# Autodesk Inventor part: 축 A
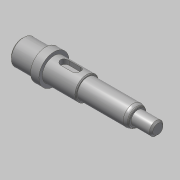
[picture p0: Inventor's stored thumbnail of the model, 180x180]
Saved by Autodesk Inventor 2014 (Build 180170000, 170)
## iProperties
Created: 2020-04
Part Number: 축 A
Material: 강철, 연강
Document SubType Name: Modeling
Designer: mduedu
Density: 7.86 g/cm^3
Appearance: 강철
Mass: 83.1664 g
Surface Area: 37.6212 cm^2
Volume: 10.581 cm^3
Author: mduedu
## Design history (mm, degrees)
sketch "스케치1"
  geometry: L1 (0, 0)-(14, 0); L2 (14, 0)-(14, 7.5); L3 (14, 7.5)-(0, 7.5); L4 (0, 7.5)-(0, 0); L5 (14, 0)-(19, 0); L6 (19, 0)-(19, 9); L7 (19, 9)-(14, 9); L8 (14, 9)-(14, 0); L9 (19, 0)-(39, 0); L10 (39, 0)-(39, 7); L11 (39, 7)-(19, 7); L12 (19, 7)-(19, 0); L13 (39, 0)-(69, 0); L14 (69, 0)-(69, 6); L15 (69, 6)-(39, 6); L16 (39, 6)-(39, 0); L17 (69, 0)-(81, 0); L18 (81, 0)-(81, 4); L19 (81, 4)-(69, 4); L20 (69, 4)-(69, 0)
  constraints: 40 end point, 10 parallel, 5 horizontal, 5 perpendicular
  dimensions: "d0" = 81 distance between parallel lines of L18 L4; "d2" = 14 distance of L2.end L3.end; "d3" = 5 distance of L6.end L7.end; "d4" = 12 distance of L18.end L19.end; "d5" = 8 diameter of L19 L17; "d6" = 12 diameter of L15 L13; "d7" = 14 diameter of L11 L9; "d8" = 15 diameter of L3 L1; "d9" = 18 diameter of L7 L5; "d10" = 42 distance between parallel lines of L10 L18
revolve "회전1" sketch "스케치1" stored, may be unused: angle "d11" = 90 deg
sketch "스케치2"
  geometry: L1 (0, -7.5)-(0, 7.5) reference; L2 (0, 7.5)-(14, 7.5) reference; L3 (14, 7.5)-(14, 9) reference; L4 (14, 9)-(19, 9) reference; L5 (19, 9)-(19, 7) reference; L6 (19, 7)-(39, 7) reference; L7 (39, 7)-(39, 6) reference; L8 (39, 6)-(69, 6) reference; L9 (69, 6)-(69, 4) reference; L10 (69, 4)-(81, 4) reference; L11 (81, 4)-(81, -4) reference; L12 (81, -4)-(69, -4) reference; L13 (69, -4)-(69, -6) reference; L14 (69, -6)-(39, -6) reference; L15 (39, -6)-(39, -7) reference; L16 (39, -7)-(19, -7) reference; L17 (19, -7)-(19, -9) reference; L18 (19, -9)-(14, -9) reference; L19 (14, -9)-(14, -7.5) reference; L20 (14, -7.5)-(0, -7.5) reference; L21 (81, -4)-(73, -4); L22 (73, -4)-(73, -2.8); L23 (73, -2.8)-(81, -2.8); L24 (81, -2.8)-(81, -4); 1 further point
  constraints: 8 end point, 2 parallel, 1 horizontal, 1 perpendicular
  dimensions: "d12" = 8 distance of L22.end L23.end; "d13" = 1.2 distance of L21.end L22.end
extrude "돌출1" cut sketch "스케치2" stored distance "d14" = 2; taper "d15" = 0 deg
fillet "모깎기1" dims "d16" = 1
sketch "스케치3"
  geometry: L1 (0, -7.5)-(0, 7.5) reference; L2 (0, 7.5)-(14, 7.5) reference; L3 (14, 7.5)-(14, 9) reference; L4 (14, 9)-(19, 9) reference; L5 (19, 9)-(19, 7) reference; L6 (19, 7)-(39, 7) reference; L7 (39, 7)-(39, 6) reference; L8 (39, 6)-(69, 6) reference; L9 (69, 6)-(69, 4) reference; L10 (69, 4)-(81, 4) reference; L11 (81, 4)-(81, -2.8) reference; L12 (81, -2.8)-(73, -2.8) reference; L13 (73, -2.8)-(73, -4) reference; L14 (73, -4)-(69, -4) reference; L15 (69, -4)-(69, -6) reference; L16 (69, -6)-(39, -6) reference; L17 (39, -6)-(39, -7) reference; L18 (39, -7)-(19, -7) reference; L19 (19, -7)-(19, -9) reference; L20 (19, -9)-(14, -9) reference; L21 (14, -9)-(14, -7.5) reference; L22 (14, -7.5)-(0, -7.5) reference; L23 (23, 7)-(35, 7); L24 (35, 7)-(35, 4); L25 (35, 4)-(23, 4); L26 (23, 4)-(23, 7); 1 further point
  constraints: 8 end point, 2 parallel, 1 horizontal, 1 perpendicular, 1 point on line
  dimensions: "d17" = 12 distance of L24.end L25.end; "d18" = 3 distance of L23.end L24.end; "d19" = 4 distance from line of L26 L4.end
extrude "돌출2" cut sketch "스케치3" stored distance "d20" = 5; taper "d21" = 0 deg
fillet "모깎기2" dims "d22" = 2.5
chamfer "모따기1" distance "d23" = 1; stored, may be unused: second distance "d24" = 2, angle "d25" = 45 deg
chamfer "모따기2" distance "d26" = 0.5; stored, may be unused: second distance "d27" = 2, angle "d28" = 45 deg
fillet "모깎기3" dims "d29" = 0.3
chamfer "모따기3" distance "d30" = 1.56; stored, may be unused: second distance "d31" = 2, angle "d32" = 30 deg
fillet "모깎기4" dims "d33" = 4, "d34" = 0.5
node "솔리드1"
node "절단 모서리 투영1"
node "절단 모서리 투영2"
